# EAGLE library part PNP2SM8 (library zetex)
Dual PNP TRANSISTOR
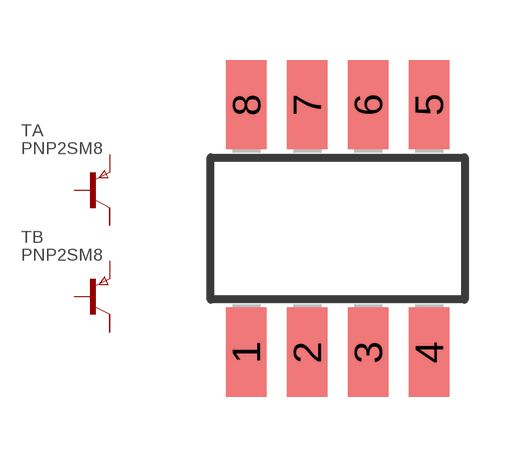
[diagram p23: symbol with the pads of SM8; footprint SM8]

Designator prefix T; gates A=PNP2C B=PNP2C

## PNP2SM8 (OC_FARNELL: unknown; OC_NEWARK: unknown)  [SM8]
1  B:E  pas
2  B:B  pas
3  A:E  pas
4  A:B  pas
5  A:C  pas
6  A:C1  pas
7  B:C  pas
8  B:C1  pas

## Footprint SM8 (pad centres in mm)
SM8 Package
smd 1.016 x 2.235: 1 -2.286,-3.099; 2 -0.762,-3.099; 3 0.762,-3.099; 4 2.286,-3.099; 5 2.286,3.099; 6 0.762,3.099; 7 -0.762,3.099; 8 -2.286,3.099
